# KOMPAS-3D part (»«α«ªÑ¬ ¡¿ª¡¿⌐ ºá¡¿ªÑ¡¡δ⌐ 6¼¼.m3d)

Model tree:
1. Эскиз:1
2. Операция выдавливания:1
     Расстояние 1 = 8
3. Эскиз:2
4. Операция выдавливания:2
     Расстояние 1 = 1
5. Эскиз:3
6. Операция выдавливания:3
     Расстояние 1 = 2.5; Угол 1 = 8
7. Эскиз:4
8. Вырезать элемент выдавливания:1
     Расстояние 1 = 20
9. Эскиз:5
10. Вырезать элемент выдавливания:2
     Расстояние 1 = 3; Угол 1 = 19
11. Скругление:1
     Радиус = 1
12. Скругление:2
     Радиус = 1
13. Скругление:3
     Радиус = 1
14. Эскиз:6
15. Эскиз:7
16. Вырезать элемент выдавливания:3
     Расстояние 2 = 30; Расстояние 1 = 60
17. Эскиз:8
18. Вырезать элемент выдавливания:4
     Расстояние 2 = 30; Расстояние 1 = 60
19. Эскиз:9
20. Операция выдавливания:4
     Расстояние 1 = 10; Расстояние 2 = 62
21. Эскиз:10
22. Вырезать элемент выдавливания:5
     Расстояние 2 = 30; Расстояние 1 = 60
23. Скругление:4
     Радиус = 2
24. Скругление:5
     Радиус = 2
25. Эскиз:11
26. Вырезать элемент выдавливания:6
     Расстояние 1 = 10
27. Эскиз:12
28. Вырезать элемент выдавливания:7
     Расстояние 1 = 2.5
29. Эскиз:13
30. Вырезать элемент выдавливания:8
     Расстояние 2 = 40; Расстояние 1 = 30
31. Эскиз:14
32. Операция выдавливания:5
     Расстояние 1 = 10; Расстояние 2 = 5.94316
33. Операция выдавливания:6
     Расстояние 1 = 2.5; Расстояние 2 = 5.94316
34. Эскиз:15
35. Вырезать элемент выдавливания:9
     Расстояние 1 = 20
36. Скругление:6
     Радиус = 1
37. Скругление:7
     Радиус = 1
